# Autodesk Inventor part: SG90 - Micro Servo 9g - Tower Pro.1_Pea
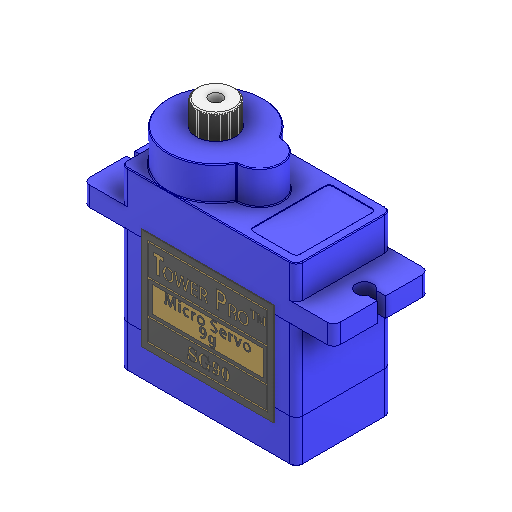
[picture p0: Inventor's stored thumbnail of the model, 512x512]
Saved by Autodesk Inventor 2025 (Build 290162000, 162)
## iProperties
Created: 2020-09
Part Number: SG90 - Micro Servo 9g - Tower Pro.1_Pea
Material: Alluminio 6061
Document SubType Name: Modeling
Designer: Ryzen5700u
Density: 2.7 g/cm^3
Appearance: Default
Author: Ryzen5700u
Revision Number: ANY
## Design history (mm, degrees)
feature "Solido1"
feature "Solido2:1"
feature "Solido3:1"
feature "Solido4:1"
feature "Solido5:1"
feature "Solido6:1"
feature "Solido7:1"
feature "Solido8:1"
feature "Solido9:1"
feature "Solido10:1"
feature "Solido11:1"
feature "Solido12:1"
feature "Solido13:1"
node "Solido2"
node "Solido3"
node "Solido4"
node "Solido5"
node "Solido6"
node "Solido7"
node "Solido8"
node "Solido9"
node "Solido10"
node "Solido11"
node "Solido12"
node "Solido13"
node "Solido14"
